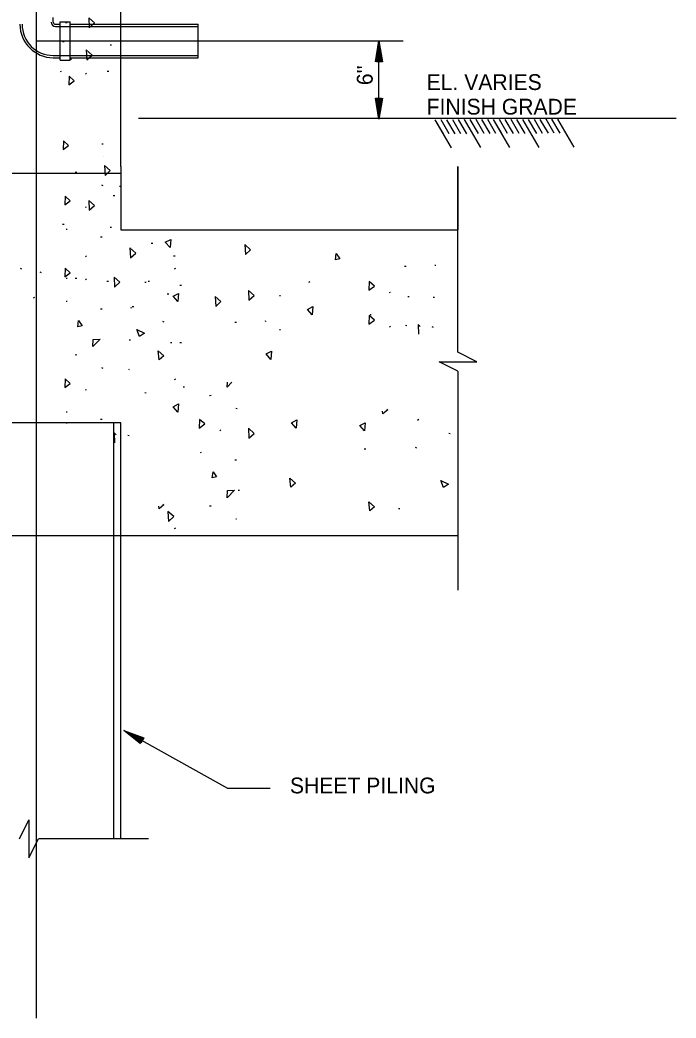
# Model space of a CAD drawing. Extents: x 22388.1 to 22405.7, y 22369.6 to 22390.4.
# Drawn here: x 22396.329 to 22398.276, y 22372.107 to 22375.068 of the extents above; entities that cross this region are included whole.
import ezdxf

# ---------------------------------------------------------------- set-up
doc = ezdxf.new("R2010")
doc.units = 0
for name, color, linetype in [('Default', 7, 'Continuous'), ('Level 1', 7, 'Continuous'), ('Level 2', 7, 'Continuous'), ('Level 3', 7, 'Continuous'), ('Level 4', 7, 'Continuous'), ('Level 44', 7, 'Continuous'), ('Level 7', 7, 'Continuous')]:
    doc.layers.add(name, color=color, linetype=linetype)

msp = doc.modelspace()

# ---------------------------------------------------------------- linework, layer by layer
at = {"layer": 'Default'}
msp.add_line((22396.3778, 22375.0052), (22397.4657, 22375.0052), dxfattribs=at)
at = {"layer": 'Level 1'}
for p, q in [((22396.3787, 22372.7735), (22396.3787, 22379.1804)), ((22397.394, 22374.773), (22397.394, 22375.0052)), ((22397.6096, 22374.6885), (22397.5612, 22374.7716)), ((22397.5854, 22374.7301), (22397.5612, 22374.7716)), ((22397.6027, 22374.7301), (22397.5785, 22374.7717)), ((22397.62, 22374.7302), (22397.5958, 22374.7717)), ((22397.6373, 22374.7303), (22397.6131, 22374.7718)), ((22397.6546, 22374.7303), (22397.6304, 22374.7719)), ((22397.6961, 22374.6889), (22397.6477, 22374.7719)), ((22397.6719, 22374.7304), (22397.6477, 22374.7719)), ((22397.6892, 22374.7305), (22397.665, 22374.772)), ((22397.7065, 22374.7305), (22397.6824, 22374.7721)), ((22397.7238, 22374.7306), (22397.6996, 22374.7721)), ((22397.7411, 22374.7307), (22397.7169, 22374.7722)), ((22397.7584, 22374.7307), (22397.7342, 22374.7723)), ((22397.7826, 22374.6892), (22397.7343, 22374.7723)), ((22397.7757, 22374.7308), (22397.7515, 22374.7724)), ((22397.793, 22374.7309), (22397.7689, 22374.7724)), ((22397.8103, 22374.731), (22397.7861, 22374.7725)), ((22397.8276, 22374.731), (22397.8034, 22374.7725)), ((22397.8691, 22374.6896), (22397.8207, 22374.7726)), ((22397.8622, 22374.7312), (22397.838, 22374.7727)), ((22397.8795, 22374.7312), (22397.8554, 22374.7728)), ((22397.8969, 22374.7313), (22397.8726, 22374.7728)), ((22397.9141, 22374.7314), (22397.8899, 22374.7729)), ((22397.9314, 22374.7314), (22397.9072, 22374.773)), ((22397.973, 22374.69), (22397.9246, 22374.773)), ((22396.3787, 22372.107), (22396.3787, 22374.5643)), ((22396.7103, 22372.6388), (22396.3843, 22372.6388))]:
    msp.add_line(p, q, dxfattribs=at)
for points in [[(22397.6287, 22374.0255), (22397.5724, 22374.0534), (22397.6848, 22374.0534), (22397.6287, 22374.0817)], [(22396.3281, 22372.6388), (22396.356, 22372.695), (22396.356, 22372.5827), (22396.3843, 22372.6388)]]:
    msp.add_lwpolyline(points, dxfattribs=at)
at = {"layer": 'Level 2'}
for p, q in [((22396.4281, 22375.0612), (22396.4281, 22375.0749)), ((22396.4346, 22375.0547), (22396.4484, 22375.0547)), ((22396.4484, 22375.0622), (22396.478, 22375.0622)), ((22396.4484, 22374.9483), (22396.4484, 22375.0622)), ((22396.478, 22374.9483), (22396.478, 22375.0622)), ((22396.478, 22375.0547), (22396.8578, 22375.0547)), ((22396.8578, 22374.9557), (22396.8578, 22375.0547)), ((22396.4346, 22375.0483), (22396.8578, 22375.0483)), ((22397.394, 22375.0052), (22397.394, 22375.0052)), ((22397.394, 22374.9879), (22397.394, 22374.9879)), ((22396.4278, 22374.9622), (22396.8578, 22374.9622)), ((22396.4281, 22374.9557), (22396.4484, 22374.9557)), ((22396.4484, 22374.9483), (22396.478, 22374.9483)), ((22396.478, 22374.9557), (22396.8578, 22374.9557)), ((22397.394, 22374.7903), (22397.394, 22374.7903)), ((22397.394, 22374.773), (22397.394, 22374.773)), ((22396.6287, 22374.6118), (22396.1287, 22374.6118)), ((22396.6287, 22374.6326), (22396.6287, 22374.4452)), ((22397.6287, 22374.0817), (22397.6287, 22374.6326)), ((22397.6287, 22374.6326), (22397.6287, 22374.4452)), ((22396.6287, 22374.4452), (22396.8162, 22374.4451)), ((22396.8162, 22374.4451), (22397.6287, 22374.4451)), ((22397.6287, 22374.0255), (22397.6287, 22373.3758)), ((22396.6287, 22373.8723), (22396.1287, 22373.8723)), ((22396.6078, 22372.6388), (22396.6078, 22373.8723)), ((22396.6287, 22372.6388), (22396.6287, 22373.8723)), ((22397.6287, 22373.5369), (22395.1287, 22373.5369)), ((22396.637, 22372.9599), (22396.637, 22372.9599)), ((22396.6522, 22372.9514), (22396.6522, 22372.9514))]:
    msp.add_line(p, q, dxfattribs=at)
for points in [[(22397.3837, 22374.9429), (22397.394, 22375.0052), (22397.4043, 22374.9429), (22397.3867, 22374.9429), (22397.394, 22374.9879), (22397.401, 22374.9456), (22397.3897, 22374.9456), (22397.394, 22374.9712), (22397.3977, 22374.9482), (22397.393, 22374.9482), (22397.394, 22374.9539)], [(22397.4043, 22374.8353), (22397.394, 22374.773), (22397.3837, 22374.8353), (22397.4013, 22374.8353), (22397.394, 22374.7903), (22397.387, 22374.8327), (22397.3983, 22374.8327), (22397.394, 22374.807), (22397.3903, 22374.83), (22397.395, 22374.83), (22397.394, 22374.8243)], [(22397.0719, 22372.7881), (22396.946, 22372.7881), (22396.637, 22372.9599)], [(22396.6865, 22372.9205), (22396.637, 22372.9599), (22396.6966, 22372.9386), (22396.688, 22372.9232), (22396.6522, 22372.9514), (22396.6926, 22372.937), (22396.6871, 22372.9271), (22396.6668, 22372.9433), (22396.6887, 22372.9354), (22396.6864, 22372.9313), (22396.6819, 22372.9349)]]:
    msp.add_lwpolyline(points, dxfattribs=at)
msp.add_lwpolyline([(22396.4744, 22374.8754), (22396.4904, 22374.8874), (22396.475, 22374.901)], close=True, dxfattribs=at)
for centre, radius in [((22396.4281, 22375.0547), 0.099), ((22396.4281, 22375.0547), 0.0925), ((22396.4346, 22375.0612), 0.0129), ((22396.4346, 22375.0612), 0.00645)]:
    msp.add_arc(centre, radius, 180, 270, dxfattribs=at)
at = {"layer": 'Level 3'}
msp.add_line((22398.2756, 22374.7752), (22396.6808, 22374.7752), dxfattribs=at)
at = {"layer": 'Level 44'}
for p, q in [((22396.4647, 22375.0603), (22396.4692, 22375.0603)), ((22396.4555, 22375.0037), (22396.46, 22375.0037)), ((22396.5966, 22374.9943), (22396.6011, 22374.9943)), ((22396.4776, 22374.9508), (22396.4821, 22374.9508)), ((22396.4493, 22374.9152), (22396.4526, 22374.9154)), ((22396.5233, 22374.9081), (22396.5269, 22374.9098)), ((22396.5882, 22374.9154), (22396.5927, 22374.9154)), ((22396.5718, 22374.7), (22396.5763, 22374.7)), ((22396.578, 22374.6624), (22396.5784, 22374.6624)), ((22396.4932, 22374.6159), (22396.4975, 22374.6166)), ((22396.5714, 22374.5781), (22396.5747, 22374.5769)), ((22396.6248, 22374.575), (22396.6293, 22374.575)), ((22396.606, 22374.5468), (22396.6105, 22374.5468)), ((22396.5233, 22374.5118), (22396.5269, 22374.5134)), ((22396.4555, 22374.462), (22396.46, 22374.462)), ((22396.4658, 22374.447), (22396.4691, 22374.4473)), ((22396.5966, 22374.4526), (22396.6011, 22374.4526)), ((22396.5683, 22374.4247), (22396.5728, 22374.4247)), ((22396.7188, 22374.4056), (22396.7233, 22374.4056)), ((22396.5233, 22374.3664), (22396.5269, 22374.3681)), ((22396.7847, 22374.3679), (22396.7892, 22374.3679)), ((22396.3294, 22374.3314), (22396.3334, 22374.3294)), ((22396.3883, 22374.3203), (22396.3923, 22374.3183)), ((22396.7874, 22374.329), (22396.7912, 22374.3313)), ((22397.4703, 22374.3369), (22397.4748, 22374.3369)), ((22397.5599, 22374.3398), (22397.5633, 22374.3403)), ((22396.4658, 22374.3017), (22396.4691, 22374.3019)), ((22396.4932, 22374.3012), (22396.4975, 22374.3019)), ((22396.5233, 22374.298), (22396.5269, 22374.2997)), ((22396.5872, 22374.2926), (22396.5917, 22374.2926)), ((22396.7001, 22374.29), (22396.7038, 22374.2897)), ((22396.7094, 22374.2926), (22396.7139, 22374.2926)), ((22397.186, 22374.2897), (22397.1898, 22374.2919)), ((22396.7659, 22374.2549), (22396.7704, 22374.2549)), ((22396.8035, 22374.2805), (22396.808, 22374.2805)), ((22397.4253, 22374.2587), (22397.4288, 22374.2603)), ((22396.3698, 22374.2432), (22396.3736, 22374.2454)), ((22396.4658, 22374.2333), (22396.4691, 22374.2335)), ((22397.0987, 22374.2507), (22397.1023, 22374.2503)), ((22397.4799, 22374.2468), (22397.4842, 22374.2468)), ((22397.5546, 22374.2452), (22397.5591, 22374.2452)), ((22396.5683, 22374.2109), (22396.5728, 22374.2109)), ((22396.658, 22374.2138), (22396.6613, 22374.2144)), ((22396.6624, 22374.2172), (22396.6669, 22374.2172)), ((22396.7523, 22374.1745), (22396.7563, 22374.1725)), ((22396.9669, 22374.1716), (22396.9714, 22374.1716)), ((22397.0566, 22374.1744), (22397.0599, 22374.175)), ((22397.3677, 22374.1939), (22397.371, 22374.1942)), ((22397.0987, 22374.1497), (22397.1023, 22374.1494)), ((22397.4253, 22374.1577), (22397.4288, 22374.1594)), ((22397.4733, 22374.1624), (22397.4766, 22374.1612)), ((22397.551, 22374.1579), (22397.5555, 22374.1567)), ((22396.578, 22374.1208), (22396.5784, 22374.1208)), ((22396.6527, 22374.1192), (22396.6572, 22374.1192)), ((22396.7753, 22374.1111), (22396.7798, 22374.1111)), ((22396.8035, 22374.1111), (22396.808, 22374.1111)), ((22396.4932, 22374.0742), (22396.4975, 22374.0749)), ((22396.5714, 22374.0364), (22396.5747, 22374.0352)), ((22396.6508, 22374.0314), (22396.6536, 22374.0307)), ((22396.7874, 22374.0011), (22396.7912, 22374.0034)), ((22396.5233, 22373.9701), (22396.5269, 22373.9718)), ((22396.7001, 22373.9621), (22396.7038, 22373.9618)), ((22396.8129, 22373.9792), (22396.8174, 22373.9792)), ((22396.8918, 22373.9539), (22396.8961, 22373.9546)), ((22396.4658, 22373.9054), (22396.4691, 22373.9056)), ((22396.97, 22373.9161), (22396.9733, 22373.9149)), ((22396.4658, 22373.8721), (22396.4691, 22373.8724)), ((22396.5683, 22373.883), (22396.5728, 22373.883)), ((22397.5086, 22373.8808), (22397.5123, 22373.883)), ((22396.9219, 22373.8498), (22396.9255, 22373.8514)), ((22397.602, 22373.8418), (22397.6057, 22373.8414)), ((22396.6491, 22373.8361), (22396.6536, 22373.8349)), ((22396.8643, 22373.785), (22396.8677, 22373.7853)), ((22397.3507, 22373.795), (22397.3552, 22373.795)), ((22397.5015, 22373.8004), (22397.5055, 22373.7984)), ((22396.9669, 22373.7627), (22396.9714, 22373.7627)), ((22396.9766, 22373.6725), (22396.9808, 22373.6725)), ((22396.8918, 22373.6259), (22396.8961, 22373.6267)), ((22397.4518, 22373.6188), (22397.4563, 22373.6188)), ((22396.97, 22373.5882), (22396.9718, 22373.5875)), ((22396.7874, 22373.559), (22396.7912, 22373.5613))]:
    msp.add_line(p, q, dxfattribs=at)
for points in [[(22396.5348, 22375.0446), (22396.5502, 22375.0588), (22396.5331, 22375.0741)], [(22396.5276, 22374.9492), (22396.543, 22374.9635), (22396.5259, 22374.9787)], [(22396.4573, 22374.683), (22396.4733, 22374.6951), (22396.458, 22374.7086)], [(22396.5818, 22374.6065), (22396.5972, 22374.6207), (22396.5801, 22374.636)], [(22396.4626, 22374.5192), (22396.4786, 22374.5313), (22396.4633, 22374.5449)], [(22396.5348, 22374.5029), (22396.5502, 22374.5171), (22396.5331, 22374.5324)], [(22396.7746, 22374.3922), (22396.7603, 22374.4082), (22396.7763, 22374.4167)], [(22396.657, 22374.3617), (22396.6725, 22374.3759), (22396.6554, 22374.3912)], [(22396.9981, 22374.3717), (22397.0136, 22374.386), (22396.9965, 22374.4012)], [(22397.2652, 22374.3564), (22397.2675, 22374.3747), (22397.2778, 22374.3594)], [(22396.4626, 22374.3054), (22396.4786, 22374.3175), (22396.4633, 22374.3311)], [(22396.61, 22374.2754), (22396.6254, 22374.2896), (22396.6083, 22374.3049)], [(22397.3645, 22374.2661), (22397.3805, 22374.2782), (22397.3652, 22374.2918)], [(22396.7976, 22374.2321), (22396.7833, 22374.2481), (22396.7992, 22374.2566)], [(22397.0086, 22374.236), (22397.024, 22374.2503), (22397.0069, 22374.2655)], [(22396.9099, 22374.2177), (22396.9253, 22374.232), (22396.9083, 22374.2472)], [(22397.1962, 22374.1927), (22397.1819, 22374.2087), (22397.1978, 22374.2173)], [(22396.501, 22374.1576), (22396.5033, 22374.1759), (22396.5136, 22374.1606)], [(22397.3645, 22374.1652), (22397.3805, 22374.1772), (22397.3652, 22374.1908)], [(22396.6842, 22374.1289), (22396.6763, 22374.1494), (22396.6983, 22374.1386)], [(22396.5468, 22374.1197), (22396.5668, 22374.1208), (22396.5451, 22374.0986)], [(22396.7388, 22374.0862), (22396.7559, 22374.0713), (22396.7417, 22374.0594)], [(22397.0736, 22374.0608), (22397.0594, 22374.0768), (22397.0753, 22374.0853)], [(22396.4626, 22373.9775), (22396.4786, 22373.9896), (22396.4633, 22374.0032)], [(22396.7976, 22373.9042), (22396.7833, 22373.9202), (22396.7992, 22373.9287)], [(22396.8612, 22373.8572), (22396.8772, 22373.8693), (22396.8618, 22373.8829)], [(22397.149, 22373.8565), (22397.1348, 22373.8725), (22397.1507, 22373.881)], [(22397.3512, 22373.8485), (22397.337, 22373.8645), (22397.3529, 22373.873)], [(22397.0086, 22373.8271), (22397.024, 22373.8414), (22397.0069, 22373.8566)], [(22396.8996, 22373.7094), (22396.9019, 22373.7276), (22396.9122, 22373.7124)], [(22397.1295, 22373.7089), (22397.1466, 22373.694), (22397.1324, 22373.6821)], [(22397.5861, 22373.6807), (22397.5782, 22373.7011), (22397.6003, 22373.6904)], [(22396.9453, 22373.6714), (22396.9653, 22373.6725), (22396.9437, 22373.6504)], [(22397.3641, 22373.6379), (22397.3812, 22373.623), (22397.3671, 22373.6111)], [(22396.7699, 22373.5802), (22396.7853, 22373.5945), (22396.7682, 22373.6097)]]:
    msp.add_lwpolyline(points, close=True, dxfattribs=at)
for points in [[(22397.5168, 22374.1587), (22397.5103, 22374.1646), (22397.5119, 22374.1351)], [(22396.9581, 22373.993), (22396.9437, 22373.9783), (22396.9448, 22373.9933)], [(22397.4175, 22373.9134), (22397.4201, 22373.9111), (22397.4059, 22373.8992), (22397.405, 22373.9075)], [(22396.6148, 22373.837), (22396.6083, 22373.8428), (22396.61, 22373.8133)], [(22396.7533, 22373.6314), (22396.7559, 22373.6292), (22396.7417, 22373.6173), (22396.7408, 22373.6255)]]:
    msp.add_lwpolyline(points, dxfattribs=at)
at = {"layer": 'Level 7'}
msp.add_line((22396.6287, 22374.6326), (22396.6287, 22376.2749), dxfattribs=at)

# ---------------------------------------------------------------- texts
at = {"layer": 'Level 4'}
for s, height, rotation, p in [("6''", 0.04688, 90, (22397.3756, 22374.8742)), ('EL. VARIES', 0.04688, 360, (22397.5357, 22374.8598)), ('FINISH GRADE', 0.046875, 360, (22397.5357, 22374.7869))]:
    msp.add_text(s, height=height, rotation=rotation, dxfattribs=at).set_placement(p)
msp.add_text('SHEET PILING', height=0.046875, dxfattribs=at).set_placement((22397.1301, 22372.7734))

doc.saveas('drawing.dxf')
